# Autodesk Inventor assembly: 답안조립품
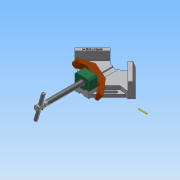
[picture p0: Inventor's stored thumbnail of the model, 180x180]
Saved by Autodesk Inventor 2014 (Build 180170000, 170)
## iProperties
Created: 2020-05
Part Number: 답안조립품
Document SubType Name: Assembly
Designer: net
Author: net
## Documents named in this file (10)
- C:\Users\net\Desktop\700506V1046\답안조립품.iam
- C:\Users\net\Desktop\700506V1046\본체.ipt
- C:\Users\net\Desktop\700506V1046\핸들.ipt
- C:\Users\net\Desktop\700506V1046\리드스크류.ipt
- C:\Users\net\Desktop\700506V1046\멈춤나사 M4x5.ipt
- C:\Users\net\Desktop\700506V1046\조.ipt
- C:\Users\net\Desktop\700506V1046\부시.ipt
- C:\Users\net\Desktop\700506V1046\평행 핀 2.5x24.ipt
- C:\Users\net\Desktop\700506V1046\서포트.ipt
- C:\Users\net\Desktop\700506V1046\볼트 M4x16.ipt
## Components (1 placed, 1 different names)
1. 핸들:1
